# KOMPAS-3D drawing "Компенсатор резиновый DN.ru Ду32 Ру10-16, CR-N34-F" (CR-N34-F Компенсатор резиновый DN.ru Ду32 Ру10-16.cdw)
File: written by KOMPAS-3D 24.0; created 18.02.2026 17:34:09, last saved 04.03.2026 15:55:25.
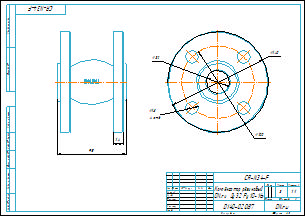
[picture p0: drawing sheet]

Document properties: Типовые: Типовые; Автор: DN.RU; Форматы листов документа: A3; Полное имя файла: CR-N34-F Компенсатор резиновый DN.ru Ду32 Ру10-16.m3d; Масса: 3; Наименование: Компенсатор резиновый DN.ru Ду32 Ру10-16; Количество листов документа: 1; Комментарий: D140-02087; Примечание: D140-02087

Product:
- Body: Твердое тело2  | qty 1
    Масса: 3.844501
- Part/product: Компенсатор резиновый DN.ru Ду32 Ру10-16  | designation CR-N34-F
    Масса: 3
    Раздел спецификации: Прочие изделия
    Комментарий: D140-02087
    Примечание: D140-02087
    additional columns: Типовые

Views: Вид 1, Спереди, Проекционный вид 2
Referenced files in E:\Работа\Зайцев\CR-N34-F Компенсатор резиновый DN.ru ДУ25-300 Ру10-16\DN32_PN10-16\: CR-N34-F Компенсатор резиновый DN.ru Ду32 Ру10-16.m3d
Referenced files in E:\Работа\Зайцев\Для компаса\: чертеж DN.ru А3.cdt
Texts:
  CR-N34-F
  чертеж DN.ru А3.cdt
  Компенсатор резиновый
  DN.ru Ду32 Ру10-16
  Твердое тело2
  Компенсатор резиновый DN.ru Ду32 Ру10-16
  CR-N34-F Компенсатор резиновый DN.ru Ду32 Ру10-16
Dimensions and other numbers on the sheet: 0; 3; 2; 4; 95; 14; 140; 100; 32; 18; 4 отв.; 1:1; 1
